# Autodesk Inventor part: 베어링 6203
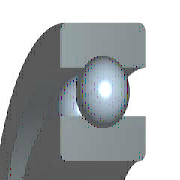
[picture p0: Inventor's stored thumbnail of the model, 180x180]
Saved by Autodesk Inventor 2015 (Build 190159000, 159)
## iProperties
IsCustomPart: 1
Company: 한국ATC센터
Created: 2009-02
Part Number: 베어링 6203
Material: Steel, Mild
Description: 깊은 그루브 볼 베어링
Document SubType Name: Modeling
Standard: KS B 2023
Designer: KYOUNG IL JANG
Standards Organization: KS
Language: ko-KR
Size Designation: 6203 - 17 x 40 x 12
Categories: <MemberInstance><Categories><Category DisplayName="샤프트 부품" InternalName="7f7aeb1f-a693-4053-b835-cee3144e0d98" Mnemonic="SHFT"><Category DisplayName="베어링" Inter
Density: 1 g/cm^3
Appearance: Steel
Author: KYOUNG IL JANG
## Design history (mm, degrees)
revolve "본체" stored, may be unused: angle "d6" = 90 deg
revolve "볼" stored, may be unused: angle "d7" = 90 deg
pattern_circular "IDS_ARRAYBALL[SIMPL:T]" dims angle "d3" = 360 deg
body "Solid1"
sketch "스케치" dims "d0" = 5.98 (= -0.26 x WD + 0.26 x BD)
  geometry: L1 (3.01, 14.25)-(8.99, 14.25); L2 (6, 14.25)-(6, 11.26); L3 (6, 14.25)-(6, 17.24); L4 (3.778, 12.249)-(0, 12.249); L5 (0, 8.5)-(12, 8.5); L6 (3.778, 16.251)-(0, 16.251); L7 (0, 20)-(12, 20); L8 (12, 8.5)-(12, 12.249); L9 (8.222, 12.249)-(12, 12.249); L10 (8.222, 16.251)-(12, 16.251); L11 (12, 20)-(12, 16.251); L12 (-1.4, 0)-(8.4, 0) reference; L13 (0, -0.3)-(0, 5.3) reference
  constraints: 22 end point, 4 point on line, 2 collinear, 2 perpendicular, 2 symmetric about line, 1 midpoint, 1 parallel, 14 other
  dimensions: "d9" = 17 diameter of L5 L12 (= WD); "d11" = 40 diameter of L7 L12 (= BD); "d12" = 12 distance between parallel lines of L8 L13 (= KB); "d13" = 24.498 diameter of L9 L12 (= 0.326 x BD + 0.674 x WD)
fillet "모깎기1" dims "d1" = 0.6 (= KRS)
other parameters: "WD" = 17 [user parameter; used in 5 equation terms], "BD" = 40 [user parameter; used in 5 equation terms], "KB" = 12 [user parameter; used in 1 equation term], "KRS" = 0.6 [user parameter; used in 1 equation term], "d4" = 0, "d5" = 0, "d8" = 0, "d14" = 0, "d15" = 0, "BBA" = 0 [user parameter], "BC0" = 4750000 [user parameter], "BC" = 9560000 [user parameter], "WR" = 8.5 (= 0.5 x WD) [user parameter]
